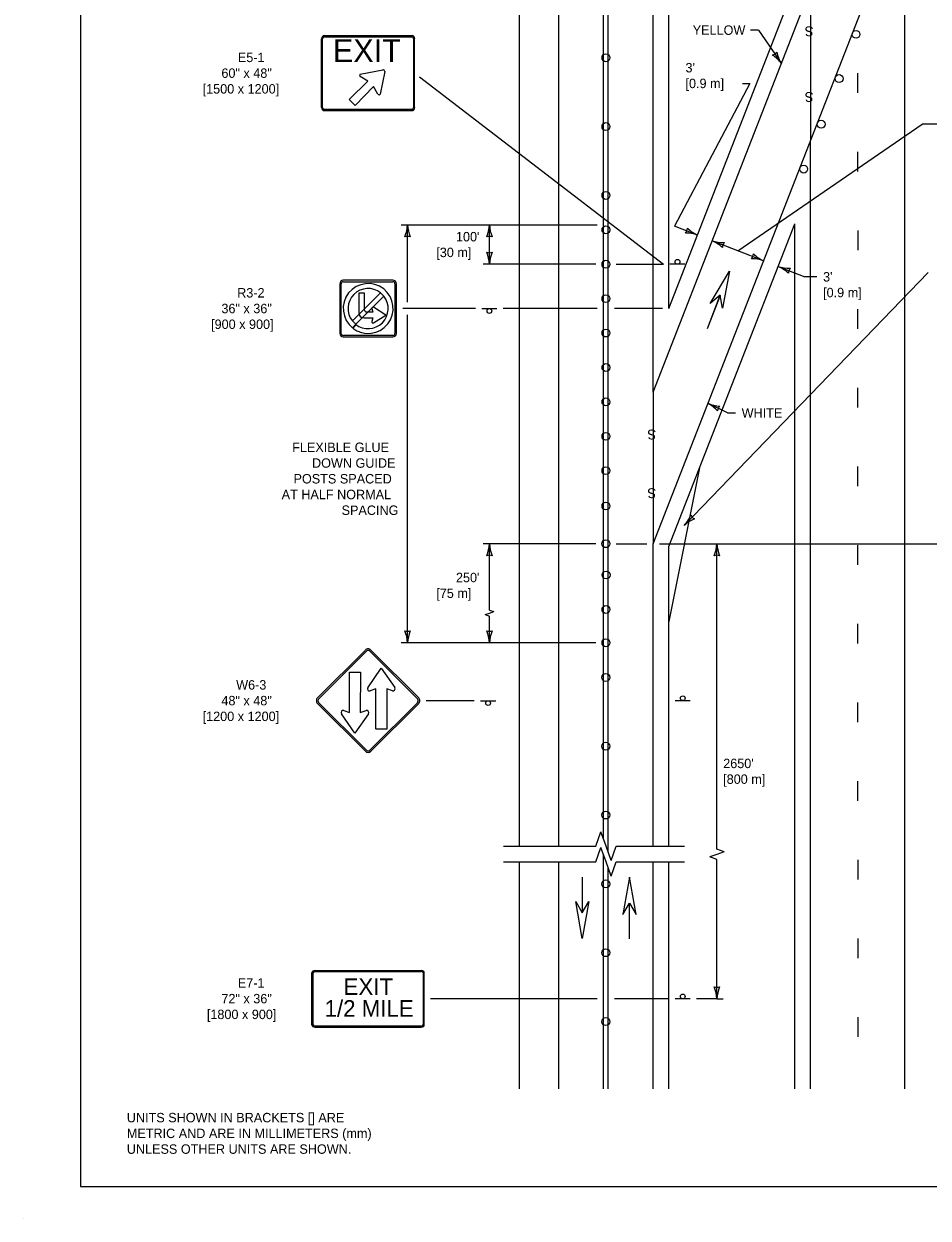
# Model space of a CAD drawing. Extents: x 49991.4 to 50021, y 49987.6 to 50011.4.
# Drawn here: x 49999.98 to 50005.72, y 49999.86 to 50007.45 of the extents above; entities that cross this region are included whole.
import ezdxf

# ---------------------------------------------------------------- set-up
doc = ezdxf.new("R2010")
doc.units = 0
for name, color, linetype in [('Level 1', 7, 'Continuous'), ('Level 2', 7, 'Continuous'), ('Level 3', 7, 'Continuous'), ('Level 6', 7, 'Continuous')]:
    doc.layers.add(name, color=color, linetype=linetype)

msp = doc.modelspace()

# ---------------------------------------------------------------- linework, layer by layer
at = {"layer": 'Level 1'}
for p, q in [((50003.9747, 50005.1129), (50003.9747, 50011.2528)), ((50004.0747, 50005.6442), (50004.0747, 50011.0628)), ((50003.1247, 50002.2265), (50003.1247, 50009.3328)), ((50003.3747, 50002.2265), (50003.3747, 50009.3328)), ((50003.6597, 50002.2708), (50003.6597, 50009.3328)), ((50003.6897, 50002.1862), (50003.6897, 50009.3328)), ((50003.9747, 50005.1129), (50005.5747, 50009.2143)), ((50003.9747, 50004.1495), (50005.5747, 50008.2511)), ((50005.5747, 50000.6846), (50005.5747, 50008.2511)), ((50004.0747, 50005.6442), (50004.8747, 50007.6956)), ((50004.9747, 50007.6763), (50004.9747, 50006.713)), ((50001.8846, 50007.3794), (50002.4432, 50007.3794)), ((50001.8682, 50006.9222), (50001.8682, 50007.3597)), ((50001.8748, 50006.9222), (50001.8748, 50007.3597)), ((50001.8846, 50007.3715), (50002.4432, 50007.3715)), ((50002.453, 50007.3597), (50002.453, 50006.9222)), ((50002.4596, 50006.9222), (50002.4596, 50007.3597)), ((50002.1127, 50007.1337), (50002.2574, 50007.1627)), ((50002.2692, 50007.1509), (50002.2403, 50007.0062)), ((50002.0426, 50006.9743), (50002.1616, 50007.0905)), ((50002.1616, 50007.0905), (50002.1127, 50007.1195)), ((50005.2747, 50007.0158), (50005.2747, 50007.1408)), ((50002.1971, 50007.0551), (50002.0808, 50006.936)), ((50002.2261, 50007.0062), (50002.1971, 50007.0551)), ((50002.0808, 50006.936), (50002.0426, 50006.9743)), ((50002.4432, 50006.9104), (50001.8846, 50006.9104)), ((50001.8846, 50006.9025), (50002.4432, 50006.9025)), ((50004.9747, 50000.6846), (50004.9747, 50006.713)), ((50005.2747, 50006.5158), (50005.2747, 50006.6408)), ((50004.0747, 50004.1308), (50004.8747, 50006.1823)), ((50004.8747, 50000.6846), (50004.8747, 50006.1823)), ((50005.2747, 50006.1407), (50005.2747, 50006.0157)), ((50004.1772, 50005.9261), (50004.0812, 50005.9261)), ((50001.9838, 50005.8019), (50001.9838, 50005.4871)), ((50001.9932, 50005.4871), (50001.9932, 50005.8019)), ((50002.3214, 50005.8245), (50002.0064, 50005.8245)), ((50002.0064, 50005.8151), (50002.3214, 50005.8151)), ((50002.3344, 50005.8019), (50002.3344, 50005.4869)), ((50002.3438, 50005.4869), (50002.3438, 50005.8019)), ((50002.0638, 50005.5655), (50002.2428, 50005.7445)), ((50002.264, 50005.7233), (50002.085, 50005.5443)), ((50002.1414, 50005.7419), (50002.1038, 50005.7419)), ((50002.1038, 50005.7419), (50002.1038, 50005.6185)), ((50002.1414, 50005.6347), (50002.1414, 50005.7419)), ((50002.2428, 50005.7445), (50002.264, 50005.7233)), ((50002.2428, 50005.7445), (50002.264, 50005.7233)), ((50004.3206, 50005.5179), (50004.4017, 50005.7289)), ((50004.3208, 50005.5179), (50004.4019, 50005.7287)), ((50002.1872, 50005.6439), (50002.1942, 50005.6219)), ((50002.2764, 50005.6031), (50002.1982, 50005.6525)), ((50002.8867, 50005.6442), (50002.9827, 50005.6442)), ((50005.2747, 50005.5158), (50005.2747, 50005.6408)), ((50002.085, 50005.5443), (50002.0638, 50005.5655)), ((50002.085, 50005.5443), (50002.0638, 50005.5655)), ((50002.1378, 50005.5845), (50002.1942, 50005.5845)), ((50002.1942, 50005.6219), (50002.154, 50005.6219)), ((50002.1942, 50005.5845), (50002.1872, 50005.5625)), ((50002.1982, 50005.5539), (50002.2764, 50005.6031)), ((50001.9838, 50005.4871), (50001.9932, 50005.4871)), ((50001.9838, 50005.4869), (50001.9932, 50005.4869)), ((50001.9932, 50005.4869), (50001.9838, 50005.4869)), ((50002.0654, 50005.5209), (50002.085, 50005.5443)), ((50002.0854, 50005.5439), (50002.066, 50005.5205)), ((50002.1982, 50005.5539), (50002.1982, 50005.5539)), ((50002.3214, 50005.4737), (50002.0064, 50005.4737)), ((50002.0064, 50005.4645), (50002.3214, 50005.4645)), ((50003.9747, 50005.1129), (50003.9747, 50004.1495)), ((50005.2747, 50005.0158), (50005.2747, 50005.1408)), ((50004.2698, 50004.6312), (50004.0747, 50003.6558)), ((50005.2747, 50004.5158), (50005.2747, 50004.6408)), ((50003.9747, 50002.2265), (50003.9747, 50004.1495)), ((50004.0747, 50002.2265), (50004.0747, 50004.1308)), ((50005.2747, 50004.0158), (50005.2747, 50004.1408)), ((50005.2747, 50003.5158), (50005.2747, 50003.6408)), ((50001.8425, 50003.1693), (50002.1465, 50003.4735)), ((50001.8494, 50003.1623), (50002.1535, 50003.4665)), ((50002.1748, 50003.4663), (50002.4787, 50003.1623)), ((50002.182, 50003.4733), (50002.4859, 50003.1693)), ((50002.1629, 50003.2343), (50002.2477, 50003.3581)), ((50002.2477, 50003.3581), (50002.3329, 50003.2345)), ((50002.0462, 50003.0769), (50002.0464, 50003.3325)), ((50002.0464, 50003.3325), (50002.1144, 50003.3323)), ((50002.1144, 50003.3323), (50002.1142, 50003.0769)), ((50002.2138, 50003.2265), (50002.1774, 50003.2149)), ((50002.2138, 50002.9711), (50002.2138, 50003.2265)), ((50002.3184, 50003.2147), (50002.2818, 50003.2263)), ((50002.2818, 50003.2263), (50002.282, 50002.9709)), ((50002.1465, 50002.8301), (50001.8424, 50003.1339)), ((50002.1535, 50002.8369), (50001.8493, 50003.1411)), ((50002.4788, 50003.1411), (50002.1748, 50002.8371)), ((50002.486, 50003.1339), (50002.1817, 50002.8301)), ((50002.8787, 50003.1517), (50002.9747, 50003.1517)), ((50004.2107, 50003.1517), (50004.1147, 50003.1517)), ((50005.2747, 50003.0158), (50005.2747, 50003.1408)), ((50002.0804, 50002.9455), (50001.9952, 50003.0691)), ((50002.0099, 50003.0887), (50002.0462, 50003.0769)), ((50002.1654, 50003.0691), (50002.0804, 50002.9455)), ((50002.1142, 50003.0769), (50002.1508, 50003.0887)), ((50002.282, 50002.9709), (50002.214, 50002.9711)), ((50005.2747, 50002.5158), (50005.2747, 50002.6408)), ((50003.6597, 50000.6846), (50003.6597, 50002.1708)), ((50005.2747, 50002.1408), (50005.2747, 50002.0158)), ((50003.1247, 50000.6846), (50003.1247, 50002.1265)), ((50003.3747, 50000.6846), (50003.3747, 50002.1265)), ((50003.6897, 50000.6846), (50003.6897, 50002.0862)), ((50003.9747, 50000.6846), (50003.9747, 50002.1265)), ((50004.0747, 50000.6846), (50004.0747, 50002.1265)), ((50003.5247, 50002.0289), (50003.5247, 50001.8031)), ((50003.5249, 50002.0289), (50003.5249, 50001.8031)), ((50003.8246, 50001.6388), (50003.8246, 50001.8646)), ((50003.8248, 50001.6388), (50003.8248, 50001.8646)), ((50005.2747, 50001.6408), (50005.2747, 50001.5158)), ((50001.8068, 50001.0913), (50001.8068, 50001.4216)), ((50001.8148, 50001.0913), (50001.8148, 50001.4216)), ((50001.8266, 50001.4365), (50002.5011, 50001.4365)), ((50001.8266, 50001.4305), (50002.5011, 50001.4305)), ((50002.513, 50001.4216), (50002.513, 50001.0913)), ((50002.5209, 50001.0913), (50002.5209, 50001.4216)), ((50004.2109, 50001.2564), (50004.1149, 50001.2564)), ((50002.5011, 50001.0824), (50001.8266, 50001.0824)), ((50001.8266, 50001.0765), (50002.5011, 50001.0765)), ((50005.2747, 50001.1408), (50005.2747, 50001.0158)), ((49999.9766, 49999.8624), (49999.9766, 49999.8624))]:
    msp.add_line(p, q, dxfattribs=at)
for points in [[(50008.6146, 50011.2628), (50000.3356, 50011.2628), (50000.3356, 50000.0624), (50008.6146, 50000.0624)], [(50004.337, 50005.6763), (50004.4606, 50005.8822), (50004.415, 50005.6464), (50004.4017, 50005.7287)], [(50003.8666, 50001.7924), (50003.8248, 50002.0288), (50003.783, 50001.7924), (50003.8248, 50001.8644)], [(50003.5667, 50001.8753), (50003.5249, 50001.6389), (50003.4831, 50001.8753), (50003.5249, 50001.8033)]]:
    msp.add_lwpolyline(points, close=True, dxfattribs=at)
for centre, radius in [((50005.2641, 50007.3875), 0.025), ((50003.6751, 50007.2386), 0.025), ((50005.1564, 50007.1064), 0.025), ((50003.6751, 50006.8011), 0.025), ((50005.0425, 50006.816), 0.025), ((50004.9313, 50006.531), 0.025), ((50003.6751, 50006.3636), 0.025), ((50003.6751, 50006.1448), 0.025), ((50003.6751, 50005.9261), 0.025), ((50004.1295, 50005.9415), 0.0152), ((50003.6751, 50005.7073), 0.025), ((50002.9343, 50005.6289), 0.0152), ((50003.6751, 50005.4886), 0.025), ((50003.6751, 50005.2698), 0.025), ((50003.6751, 50005.0511), 0.025), ((50003.6751, 50004.8323), 0.025), ((50003.6751, 50004.6136), 0.025), ((50003.6751, 50004.3892), 0.025), ((50003.6748, 50004.1495), 0.025), ((50003.6758, 50003.9504), 0.025), ((50003.6751, 50003.7316), 0.025), ((50003.6751, 50003.5198), 0.025), ((50003.6743, 50003.2996), 0.025), ((50002.9263, 50003.1363), 0.0152), ((50004.1631, 50003.1671), 0.0152), ((50003.6743, 50002.8621), 0.025), ((50003.6743, 50002.4246), 0.025), ((50003.6742, 50001.9869), 0.025), ((50003.6742, 50001.5494), 0.025), ((50004.1633, 50001.2717), 0.0152), ((50003.6742, 50001.1119), 0.025)]:
    msp.add_circle(centre, radius, dxfattribs=at)
for centre, radius, start, end in [((50002.2594, 50007.1528), 0.01, 348.70901, 101.28548), ((50002.1198, 50007.1266), 0.01, 135, 225), ((50002.2332, 50007.0133), 0.01, 225, 315), ((50002.0063, 50005.8018), 0.0225, 90, 180), ((50002.0063, 50005.8018), 0.0131, 90, 180), ((50002.1642, 50005.6448), 0.1585, 231.65928, 231.42697), ((50002.3213, 50005.8018), 0.0225, 0, 90), ((50002.3213, 50005.8018), 0.0131, 0, 90), ((50002.1638, 50005.6443), 0.1275, 51.75713, 218.2435), ((50002.1638, 50005.6443), 0.1275, 139.12855, 139.14364), ((50002.1638, 50005.6443), 0.1275, 232.04534, 38.24287), ((50002.154, 50005.6346), 0.0128, 180, 270), ((50002.1942, 50005.6461), 0.00742, 57.75616, 197.61961), ((50002.1378, 50005.6184), 0.034, 180, 270), ((50002.1942, 50005.5601), 0.00742, 162.38136, 302.24299), ((50002.0063, 50005.4868), 0.0225, 180, 270), ((50002.0063, 50005.4868), 0.0131, 180, 270), ((50002.1638, 50005.6443), 0.1275, 315.58365, 315.71312), ((50002.3213, 50005.4868), 0.0225, 270, 0), ((50002.3213, 50005.4868), 0.0131, 270, 0), ((50002.1639, 50003.4558), 0.025, 44.9951, 134.9951), ((50002.1639, 50003.4558), 0.015, 44.9951, 134.9951), ((50002.1732, 50003.227), 0.0129, 145.58005, 216.71144), ((50002.1732, 50003.227), 0.0129, 216.71449, 287.95328), ((50002.3221, 50003.227), 0.0129, 252.03692, 323.27266), ((50002.3221, 50003.227), 0.0129, 323.27571, 34.51451), ((50001.8598, 50003.1517), 0.025, 134.99486, 224.9951), ((50001.8598, 50003.1517), 0.015, 134.99486, 224.9951), ((50002.4679, 50003.1517), 0.015, 314.9951, 44.9951), ((50002.4679, 50003.1517), 0.025, 314.9951, 44.9951), ((50002.0057, 50003.0765), 0.0129, 143.27571, 214.51451), ((50002.0057, 50003.0765), 0.0129, 72.03692, 143.27266), ((50002.1546, 50003.0764), 0.0129, 36.71449, 107.95328), ((50002.1546, 50003.0764), 0.0129, 325.58005, 36.71144), ((50002.1639, 50002.8477), 0.025, 224.99553, 314.9951), ((50002.1639, 50002.8477), 0.015, 224.99553, 314.9951)]:
    msp.add_arc(centre, radius, start, end, dxfattribs=at)
for centre, major_axis, ratio, start_param, end_param in [((50001.8846, 50007.3597), (0, 0.0197), 0.833482, 0.000008, 1.570796), ((50002.4432, 50007.3597), (0, -0.0197), 0.833482, 1.570792, 3.141593), ((50001.8846, 50007.3597), (0, 0.0118), 0.833482, 0.000008, 1.570796), ((50002.4432, 50007.3597), (0, -0.0118), 0.833482, 1.570792, 3.141593), ((50001.8846, 50006.9222), (0, -0.0197), 0.833482, 4.712389, 6.283185), ((50001.8846, 50006.9222), (0, -0.0118), 0.833482, 4.712389, 6.283185), ((50002.4432, 50006.9222), (0, -0.0118), 0.833482, 0, 1.570796), ((50002.4432, 50006.9222), (0, -0.0197), 0.833482, 0, 1.570796), ((50001.8266, 50001.4216), (-0.0198, 0), 0.750074, 4.712396, 6.283185), ((50001.8266, 50001.4216), (-0.0119, 0), 0.750074, 4.712396, 6.283185), ((50002.5011, 50001.4216), (0.0198, 0), 0.750074, 6.283181, 7.853982), ((50002.5011, 50001.4216), (0.0119, 0), 0.750074, 6.283181, 7.853982), ((50001.8266, 50001.0913), (0.0198, 0), 0.750074, 3.141593, 4.712389), ((50001.8266, 50001.0913), (0.0119, 0), 0.750074, 3.141593, 4.712389), ((50002.5011, 50001.0913), (0.0119, 0), 0.750074, 4.712389, 6.283185), ((50002.5011, 50001.0913), (0.0198, 0), 0.750074, 4.712389, 6.283185)]:
    msp.add_ellipse(centre, major_axis=major_axis, ratio=ratio, start_param=start_param, end_param=end_param, dxfattribs=at)
at = {"layer": 'Level 3'}
for p, q in [((50004.6445, 50007.4144), (50004.5945, 50007.4144)), ((50004.6445, 50007.4144), (50004.7899, 50007.2024)), ((50002.4913, 50007.1166), (50004.0412, 50005.9261)), ((50004.59, 50007.0756), (50004.1116, 50006.1687)), ((50004.5417, 50007.0756), (50004.59, 50007.0756)), ((50004.5134, 50006.012), (50005.6844, 50006.816)), ((50006.0347, 50006.816), (50005.6844, 50006.816)), ((50002.3742, 50006.1761), (50003.6197, 50006.1761)), ((50002.4142, 50005.6842), (50002.4142, 50006.1761)), ((50002.9347, 50005.9261), (50002.9347, 50006.1761)), ((50004.2571, 50006.1119), (50004.1116, 50006.1687)), ((50004.6765, 50005.9484), (50004.3503, 50006.0756)), ((50003.6101, 50005.9261), (50002.8947, 50005.9261)), ((50003.7401, 50005.9261), (50004.0412, 50005.9261)), ((50005.7221, 50005.8741), (50004.1727, 50004.2653)), ((50004.7693, 50005.9122), (50004.9386, 50005.8462)), ((50005.0148, 50005.8462), (50004.9386, 50005.8462)), ((50002.8467, 50005.6442), (50002.3838, 50005.6442)), ((50003.6197, 50005.6442), (50003.0227, 50005.6442)), ((50004.0347, 50005.6442), (50003.7297, 50005.6442)), ((50002.4142, 50003.5198), (50002.4142, 50005.6042)), ((50004.4474, 50004.9808), (50004.3229, 50005.042)), ((50004.4474, 50004.9808), (50004.4974, 50004.9808)), ((50003.6098, 50004.1495), (50002.8947, 50004.1495)), ((50002.9347, 50003.7279), (50002.9347, 50004.1495)), ((50003.7398, 50004.1495), (50003.9347, 50004.1495)), ((50004.0147, 50004.1495), (50006.1147, 50004.1495)), ((50004.38, 50002.207), (50004.38, 50004.1494)), ((50002.9074, 50003.6988), (50002.9348, 50003.7085)), ((50002.9074, 50003.6988), (50002.9348, 50003.6891)), ((50002.9347, 50003.5198), (50002.9347, 50003.6891)), ((50002.9348, 50003.7279), (50002.9622, 50003.7182)), ((50002.9348, 50003.7085), (50002.9622, 50003.7182)), ((50003.6101, 50003.5198), (50002.3742, 50003.5198)), ((50002.8387, 50003.1517), (50002.5329, 50003.1517)), ((50004.38, 50002.1746), (50004.3344, 50002.1584)), ((50004.38, 50002.1422), (50004.3344, 50002.1584)), ((50004.4258, 50002.1908), (50004.38, 50002.207)), ((50004.4258, 50002.1908), (50004.38, 50002.1746)), ((50004.38, 50001.2564), (50004.38, 50002.1422)), ((50003.6197, 50001.2564), (50002.5609, 50001.2564)), ((50004.0749, 50001.2564), (50003.7297, 50001.2564)), ((50004.38, 50001.2564), (50004.2509, 50001.2564)), ((50004.38, 50001.2564), (50004.42, 50001.2564))]:
    msp.add_line(p, q, dxfattribs=at)
for centre, radius, start, end in [((50004.7174, 50007.3082), 0.0548, 286.58645, 322.30881), ((50004.6045, 50007.0613), 0.233, 37.27494, 56.52479), ((50004.9782, 50007.3205), 0.2223, 191.90364, 212.08715), ((50002.192, 50006.1852), 0.2223, 337.45601, 357.63952), ((50002.6469, 50006.1876), 0.233, 182.82731, 202.07716), ((50002.7126, 50006.1852), 0.2223, 337.45601, 357.63952), ((50003.1674, 50006.1876), 0.233, 182.82731, 202.07716), ((50002.4142, 50006.0479), 0.0548, 72.13882, 107.86118), ((50002.9347, 50006.0479), 0.0548, 72.13882, 107.86118), ((50004.1376, 50006.1585), 0.0548, 320.83415, 356.55651), ((50004.1849, 50005.9017), 0.2223, 71.05581, 91.23932), ((50004.3523, 50006.3246), 0.233, 226.61817, 245.86802), ((50004.261, 50005.872), 0.2223, 46.14604, 66.32954), ((50004.4242, 50006.2966), 0.233, 251.51734, 270.76719), ((50004.4697, 50006.029), 0.0548, 140.82884, 176.55121), ((50002.9347, 50006.0543), 0.0548, 252.13882, 287.86118), ((50002.702, 50005.9146), 0.233, 2.82731, 22.07716), ((50003.1569, 50005.9169), 0.2223, 157.45601, 177.63952), ((50004.5569, 50005.9948), 0.0548, 320.91902, 356.64138), ((50004.6046, 50005.738), 0.2223, 71.14068, 91.32419), ((50004.7714, 50006.1611), 0.233, 226.70304, 245.95289), ((50004.8415, 50006.1224), 0.2223, 251.05581, 271.23932), ((50004.6741, 50005.6995), 0.233, 46.61817, 65.86802), ((50004.8888, 50005.8656), 0.0548, 140.83415, 176.55651), ((50004.2168, 50004.8466), 0.2223, 41.31383, 61.49734), ((50004.4151, 50005.2559), 0.233, 246.68513, 265.93498), ((50004.438, 50004.9855), 0.0548, 135.99664, 171.719), ((50003.9972, 50004.4184), 0.233, 318.90623, 338.15608), ((50004.3264, 50004.1046), 0.2223, 113.53493, 133.71844), ((50004.2617, 50004.3576), 0.0548, 208.21774, 243.9401), ((50002.702, 50004.161), 0.233, 337.92284, 357.17269), ((50003.1569, 50004.1586), 0.2223, 182.36048, 202.54399), ((50004.1472, 50004.161), 0.233, 337.92284, 357.17269), ((50004.6021, 50004.1586), 0.2223, 182.36048, 202.54399), ((50002.9347, 50004.0213), 0.0548, 72.13882, 107.86118), ((50004.38, 50004.0213), 0.0548, 72.13882, 107.86118), ((50002.192, 50003.5107), 0.2223, 2.36048, 22.54399), ((50002.4142, 50003.648), 0.0548, 252.13882, 287.86118), ((50002.6469, 50003.5083), 0.233, 157.92284, 177.17269), ((50002.7126, 50003.5107), 0.2223, 2.36048, 22.54399), ((50002.9347, 50003.648), 0.0548, 252.13882, 287.86118), ((50003.1674, 50003.5083), 0.233, 157.92284, 177.17269), ((50004.1578, 50001.2472), 0.2223, 2.36048, 22.54399), ((50004.38, 50001.3846), 0.0548, 252.13882, 287.86118), ((50004.6127, 50001.2449), 0.233, 157.92284, 177.17269)]:
    msp.add_arc(centre, radius, start, end, dxfattribs=at)
at = {"layer": 'Level 6'}
for p, q in [((50003.6106, 50002.2265), (50003.643, 50002.3179)), ((50003.6754, 50002.2265), (50003.643, 50002.3179)), ((50003.0247, 50002.2265), (50003.6106, 50002.2265)), ((50003.6106, 50002.1265), (50003.643, 50002.2179)), ((50003.6754, 50002.1265), (50003.643, 50002.2179)), ((50003.7078, 50002.1351), (50003.6754, 50002.2265)), ((50003.7078, 50002.1351), (50003.7402, 50002.2265)), ((50003.7402, 50002.2265), (50004.1747, 50002.2265)), ((50003.0247, 50002.1265), (50003.6106, 50002.1265)), ((50003.7078, 50002.0351), (50003.6754, 50002.1265)), ((50003.7078, 50002.0351), (50003.7402, 50002.1265)), ((50003.7402, 50002.1265), (50004.1747, 50002.1265))]:
    msp.add_line(p, q, dxfattribs=at)

# ---------------------------------------------------------------- texts
at = {"layer": 'Level 1'}
for p in [(50004.994, 50007.4384), (50004.994, 50007.0204), (50003.994, 50004.875), (50003.994, 50004.5021)]:
    msp.add_text('S', height=0.0625, rotation=180, dxfattribs=at).set_placement(p)
for s, height, p in [('EXIT', 0.1452, (50001.9402, 50007.2111)), ('EXIT', 0.10585, (50002.0079, 50001.2808)), ('1/2 MILE', 0.10585, (50001.8872, 50001.1421))]:
    msp.add_text(s, height=height, dxfattribs=at).set_placement(p)
at = {"layer": 'Level 2'}
for s, p in [('YELLOW', (50004.2263, 50007.3844)), ('E5-1', (50001.3361, 50007.211)), ('60" x 48"', (50001.2317, 50007.111)), ('[1500 x 1200]', (50001.1123, 50007.011)), ("100'", (50002.722, 50006.0713)), ('[30 m]', (50002.597, 50005.9713)), ('R3-2', (50001.3318, 50005.7146)), ('36" x 36"', (50001.2317, 50005.6146)), ('[900 x 900]', (50001.1661, 50005.5146)), ('WHITE', (50004.5374, 50004.9508)), ('FLEXIBLE GLUE', (50001.6814, 50004.7324)), ('DOWN GUIDE', (50001.8074, 50004.6324)), ('POSTS SPACED', (50001.69, 50004.5324)), ('AT HALF NORMAL', (50001.6145, 50004.4324)), ('SPACING', (50001.9953, 50004.3324)), ("250'", (50002.722, 50003.9047)), ('[75 m]', (50002.597, 50003.8047)), ('W6-3', (50001.3255, 50003.2221)), ('48" x 48"', (50001.2317, 50003.1221)), ('[1200 x 1200]', (50001.1123, 50003.0221)), ("2650'", (50004.42, 50002.7229)), ('[800 m]', (50004.42, 50002.6229)), ('E7-1', (50001.3361, 50001.3276)), ('72" x 36"', (50001.2317, 50001.2276)), ('[1800 x 900]', (50001.1392, 50001.1276)), ('UNITS SHOWN IN BRACKETS [] ARE ', (50000.6306, 50000.4713)), ('METRIC AND ARE IN MILLIMETERS (mm) ', (50000.6306, 50000.3713)), ('UNLESS OTHER UNITS ARE SHOWN.', (50000.6306, 50000.2713))]:
    msp.add_text(s, height=0.06, dxfattribs=at).set_placement(p)
for s, p in [("3'", (50004.1804, 50007.1456)), ('[0.9 m]', (50004.1804, 50007.0456)), ("3'", (50005.0548, 50005.8162)), ('[0.9 m]', (50005.0548, 50005.7162))]:
    msp.add_text(s, height=0.06, rotation=360, dxfattribs=at).set_placement(p)

doc.saveas('drawing.dxf')
